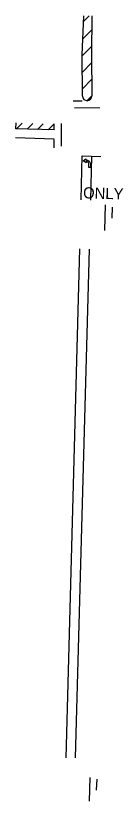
# Model space of a CAD drawing. Extents: x 979036 to 996074, y 1836928 to 1845163.
# Drawn here: x 992455 to 992595, y 1844146 to 1845163 of the extents above; entities that cross this region are included whole.
import ezdxf

# ---------------------------------------------------------------- set-up
doc = ezdxf.new("R2010")
doc.units = 0
for name, color, linetype in [('STRIPE_White Crosswalk', 7, 'Continuous'), ('STRIPE_White Stopbar', 7, 'Continuous'), ('STRIPE_White Turn Arrow', 7, 'Continuous'), ('STRIPE_White_6in', 7, 'Continuous'), ('STRIPE_White_ONLY', 7, 'Continuous'), ('STRIPE_Yellow Dbl 6in', 7, 'Continuous'), ('STRIPE_Yellow_10_30 SKIP', 7, 'Continuous'), ('STRIPE_Yellow_6in', 7, 'Continuous')]:
    doc.layers.add(name, color=color, linetype=linetype)

msp = doc.modelspace()

# ---------------------------------------------------------------- linework, layer by layer
at = {"layer": 'STRIPE_White Crosswalk'}
for p, q in [((992564.7, 1845043.4), (992531.5, 1845043.1)), ((992514.2, 1845023.3), (992514.2, 1844993.7)), ((992570.9, 1844884.9), (992572.1, 1844918.1)), ((992550.9, 1844145.7), (992552, 1844176.7))]:
    msp.add_line(p, q, dxfattribs=at)
at = {"layer": 'STRIPE_White Stopbar'}
for p, q in [((992541.7, 1845052.2), (992530, 1845052.1)), ((992505.2, 1844991.9), (992505.2, 1845002.7)), ((992541.8, 1844981.2), (992565.8, 1844980.6)), ((992580.5, 1844900.9), (992580.9, 1844915)), ((992560.4, 1844160.2), (992560.9, 1844174.2))]:
    msp.add_line(p, q, dxfattribs=at)
at = {"layer": 'STRIPE_White Turn Arrow'}
msp.add_lwpolyline([(992546.6, 1844972.4), (992543, 1844974.8), (992546.2, 1844977.7), (992546.3, 1844976), (992547, 1844976), (992547.6, 1844975.9), (992548.4, 1844975.7), (992549.3, 1844975.3), (992550, 1844974.9), (992550.6, 1844974.3), (992551.3, 1844973.7), (992551.7, 1844973), (992552.1, 1844972.2), (992552.3, 1844971.3), (992552.4, 1844970.3), (992552.2, 1844966.4), (992550.2, 1844966.5), (992550.4, 1844970.1), (992550.3, 1844970.8), (992550.2, 1844971.5), (992549.8, 1844972.3), (992549.2, 1844973), (992549, 1844973.2), (992548.4, 1844973.6), (992547.6, 1844973.9), (992546.9, 1844974), (992546.5, 1844974)], close=True, dxfattribs=at)
at = {"layer": 'STRIPE_White_6in'}
for p, q in [((992455.6, 1845016.5), (992455.8, 1845024)), ((992463.7, 1845023.8), (992456.4, 1845016.5)), ((992477.4, 1845023.4), (992470.1, 1845016)), ((992491.1, 1845022.9), (992483.7, 1845015.6)), ((992505.2, 1845022.9), (992497.4, 1845015.1)), ((992505.2, 1845014.9), (992505.2, 1845022.9)), ((992505.2, 1845014.9), (992455.6, 1845016.5)), ((992553.8, 1844980.9), (992552.3, 1844924))]:
    msp.add_line(p, q, dxfattribs=at)
at = {"layer": 'STRIPE_Yellow Dbl 6in'}
for p, q in [((992541.6, 1845112.2), (992543.6, 1845162.8)), ((992554.3, 1845162.5), (992553.6, 1845113.1)), ((992542, 1845058.8), (992541.6, 1845112.8)), ((992553.6, 1845112.9), (992554, 1845058.9)), ((992505.2, 1845002.8), (992455.2, 1845004.5)), ((992540.3, 1844924.3), (992541.8, 1844981.2))]:
    msp.add_line(p, q, dxfattribs=at)
msp.add_arc((992548, 1845058.8), 6, 180.4194, 0.4194, dxfattribs=at)
at = {"layer": 'STRIPE_Yellow_10_30 SKIP'}
for p, q in [((992520.7, 1844202), (992538.6, 1844861.1)), ((992550.6, 1844860.7), (992532.7, 1844202))]:
    msp.add_line(p, q, dxfattribs=at)
at = {"layer": 'STRIPE_Yellow_6in'}
for p, q in [((992550.7, 1845162.8), (992543.3, 1845155.2)), ((992554, 1845144.7), (992542.4, 1845132.9)), ((992553.7, 1845123.1), (992541.6, 1845110.8)), ((992553.7, 1845101.6), (992541.8, 1845089.5)), ((992553.8, 1845080.4), (992541.9, 1845068.3)), ((992554, 1845059.2), (992547.7, 1845052.8))]:
    msp.add_line(p, q, dxfattribs=at)

# ---------------------------------------------------------------- texts
at = {"layer": 'STRIPE_White_ONLY'}
msp.add_text('ONLY', height=14.4, rotation=358.1709, dxfattribs=at).set_placement((992542.6, 1844926.5))

doc.saveas('drawing.dxf')
